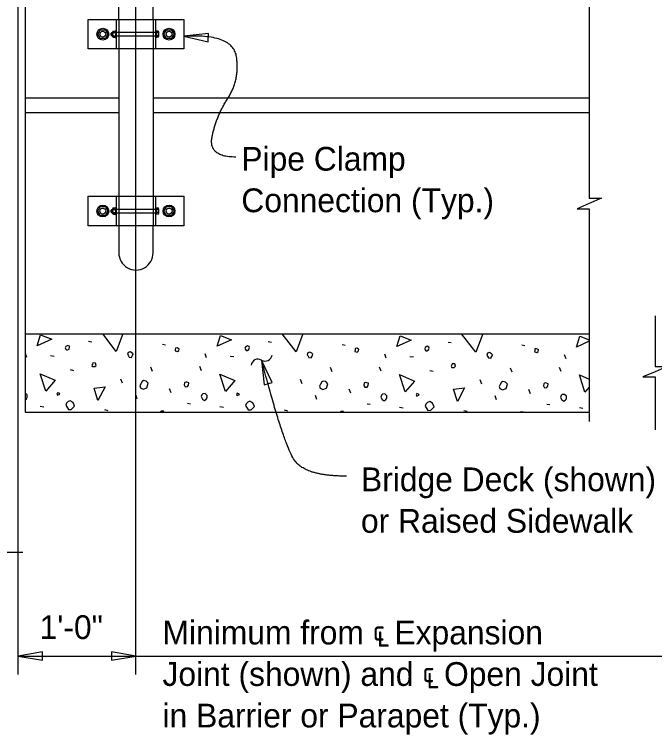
# Model space of a CAD drawing. Extents: x 0.2 to 40.8, y 0.5 to 25.7.
# Drawn here: x 23.58 to 29.01, y 10.82 to 16.93 of the extents above; entities that cross this region are included whole.
import ezdxf

# ---------------------------------------------------------------- set-up
doc = ezdxf.new("R2010")
doc.units = 0
for name, color, linetype in [('CL_Major', 7, 'Continuous'), ('Dimension', 7, 'Continuous'), ('Miscellaneous', 7, 'Continuous'), ('SteelMisc', 7, 'Continuous'), ('SteelMisc_h', 7, 'Continuous'), ('SupstrConc', 7, 'Continuous'), ('TextStructures', 7, 'Continuous')]:
    doc.layers.add(name, color=color, linetype=linetype)

msp = doc.modelspace()

# ---------------------------------------------------------------- linework, layer by layer
at = {"layer": 'CL_Major'}
for p, q in [((24.6151, 11.3358), (24.6151, 25.0052)), ((23.6151, 11.3358), (23.6151, 17.2313))]:
    msp.add_line(p, q, dxfattribs=at)
at = {"layer": 'Dimension'}
msp.add_line((23.6151, 11.4901), (29.4153, 11.4901), dxfattribs=at)
for points in [[(28.4596, 17.2246), (28.4596, 15.3737), (28.5629, 15.3737), (28.4596, 15.3287), (28.3562, 15.2837), (28.4596, 15.2837), (28.4596, 13.4788)], [(29.0176, 14.3746), (29.0176, 13.9474), (29.1209, 13.9474), (29.0176, 13.9024), (28.9142, 13.8574), (29.0176, 13.8574), (29.0176, 13.4079)], [(23.6547, 12.3699), (22.9577, 12.3699), (22.9577, 12.2536), (22.8583, 12.4786), (22.8583, 12.3699), (22.2031, 12.3699)]]:
    msp.add_lwpolyline(points, dxfattribs=at)
for points in [[(25.0211, 16.7461), (25.2271, 16.6998), (25.2309, 16.7703)], [(25.6811, 14.0008), (25.7034, 13.7907), (25.7713, 13.8098)], [(23.6151, 11.4901), (23.8234, 11.4549), (23.8234, 11.5254)], [(24.6151, 11.4902), (24.4069, 11.5255), (24.4069, 11.4549)]]:
    msp.add_lwpolyline(points, close=True, dxfattribs=at)
for centre, start, end in [((25.6504, 13.9489), 59.84335, 171.57057), ((25.7103, 14.052), 239.84335, 351.57057)]:
    msp.add_arc(centre, 0.0596, start, end, dxfattribs=at)
for points in [[(25.4627, 15.7225), (25.2257, 15.7202), (25.2971, 16.0714), (25.4956, 16.3764), (25.4402, 16.7692), (25.021, 16.7461)], [(26.3997, 13.0164), (26.0593, 13.0164), (25.8702, 13.2719), (25.6811, 14.0007)]]:
    msp.add_open_spline(points, degree=2, dxfattribs=at)
at = {"layer": 'Miscellaneous'}
for p, q in [((24.4075, 16.7575), (24.4075, 16.7696)), ((24.4132, 16.7575), (24.4132, 16.7696)), ((24.4075, 15.2575), (24.4075, 15.2696)), ((24.4132, 15.2575), (24.4132, 15.2696)), ((24.2137, 14.1609), (24.2402, 14.1556)), ((24.8395, 14.1361), (24.866, 14.1308)), ((25.7375, 14.1573), (25.7641, 14.152)), ((26.3633, 14.1326), (26.3898, 14.1273)), ((27.2613, 14.1538), (27.2879, 14.1485)), ((27.8871, 14.129), (27.9137, 14.1237)), ((23.6905, 14.023), (23.6781, 14.0566)), ((25.2143, 14.0194), (25.2019, 14.053)), ((26.7381, 14.0159), (26.7257, 14.0495)), ((23.8902, 14.0389), (23.922, 14.0353)), ((25.414, 14.0353), (25.4459, 14.0318)), ((26.9378, 14.0318), (26.9697, 14.0283)), ((28.2619, 14.0124), (28.2495, 14.046)), ((24.7564, 13.9045), (24.7423, 13.9399)), ((25.1718, 13.9098), (25.1577, 13.9452)), ((26.2802, 13.901), (26.2661, 13.9364)), ((26.6957, 13.9063), (26.6815, 13.9417)), ((27.8041, 13.8975), (27.7899, 13.9328)), ((28.2195, 13.9028), (28.2053, 13.9381)), ((24.0582, 13.9204), (24.0864, 13.9134)), ((27.1058, 13.9134), (27.1341, 13.9063)), ((24.5001, 13.8038), (24.486, 13.8391)), ((26.0239, 13.8002), (26.0098, 13.8356)), ((27.5477, 13.7967), (27.5336, 13.8321)), ((24.9138, 13.7225), (24.8996, 13.7578)), ((26.4376, 13.7189), (26.4234, 13.7543)), ((27.9614, 13.7154), (27.9472, 13.7507)), ((24.6256, 13.6712), (24.6132, 13.7048)), ((26.1494, 13.6677), (26.137, 13.7012)), ((27.6732, 13.6641), (27.6609, 13.6977)), ((25.0516, 13.6341), (25.0764, 13.6305)), ((26.5755, 13.6305), (26.6002, 13.627)), ((28.0993, 13.627), (28.124, 13.6235)), ((23.8036, 13.6093), (23.8336, 13.604)), ((24.3481, 13.581), (24.3764, 13.574)), ((25.3274, 13.6058), (25.3575, 13.6005)), ((25.8719, 13.5775), (25.9002, 13.5704)), ((26.8512, 13.6022), (26.8813, 13.5969)), ((27.3957, 13.574), (27.424, 13.5669)), ((28.375, 13.5987), (28.4051, 13.5934))]:
    msp.add_line(p, q, dxfattribs=at)
for points in [[(23.7788, 14.122), (23.8071, 14.2139), (23.9008, 14.1768), (23.7788, 14.122)], [(24.4488, 14.0742), (24.3346, 14.2245)], [(24.505, 14.2245), (24.4488, 14.0742)], [(25.3027, 14.1184), (25.3309, 14.2104), (25.4246, 14.1732), (25.3027, 14.1184)], [(25.9726, 14.0707), (25.8558, 14.2245)], [(26.0301, 14.2245), (25.9726, 14.0707)], [(26.8265, 14.1149), (26.8548, 14.2068), (26.9485, 14.1697), (26.8265, 14.1149)], [(27.4965, 14.0672), (27.3769, 14.2245)], [(27.5553, 14.2245), (27.4965, 14.0672)], [(28.3503, 14.1114), (28.3786, 14.2033), (28.4595, 14.1712)], [(24.0263, 14.0866), (24.0334, 14.0866), (24.0475, 14.0937), (24.0529, 14.1096), (24.0511, 14.1184), (24.0369, 14.1255), (24.0193, 14.1149), (24.0157, 14.1043), (24.0193, 14.0937), (24.0263, 14.0866)], [(25.5502, 14.0831), (25.5572, 14.0831), (25.5714, 14.0901), (25.5767, 14.1061), (25.5749, 14.1149), (25.5608, 14.122), (25.5431, 14.1114), (25.5395, 14.1008), (25.5431, 14.0901), (25.5502, 14.0831)], [(27.074, 14.0795), (27.081, 14.0795), (27.0952, 14.0866), (27.1005, 14.1025), (27.0987, 14.1114), (27.0846, 14.1184), (27.0669, 14.1078), (27.0634, 14.0972), (27.0669, 14.0866), (27.074, 14.0795)], [(28.4595, 14.1604), (28.3503, 14.1114)], [(24.5478, 14.0424), (24.5567, 14.0265), (24.5779, 14.023), (24.5867, 14.0389), (24.5903, 14.053), (24.5814, 14.0619), (24.5655, 14.0707), (24.5496, 14.0654), (24.5443, 14.0495), (24.5478, 14.0424)], [(24.9473, 14.0778), (24.9668, 14.0725), (24.9792, 14.0813), (24.9809, 14.0937), (24.9774, 14.0972), (24.9633, 14.1043), (24.9509, 14.1025), (24.9491, 14.0901), (24.9473, 14.0778)], [(26.0716, 14.0389), (26.0805, 14.023), (26.1017, 14.0194), (26.1105, 14.0353), (26.1141, 14.0495), (26.1052, 14.0583), (26.0893, 14.0672), (26.0734, 14.0619), (26.0681, 14.046), (26.0716, 14.0389)], [(26.4712, 14.0742), (26.4906, 14.0689), (26.503, 14.0778), (26.5047, 14.0901), (26.5012, 14.0937), (26.4871, 14.1008), (26.4747, 14.099), (26.4729, 14.0866), (26.4712, 14.0742)], [(27.5955, 14.0353), (27.6043, 14.0194), (27.6255, 14.0159), (27.6343, 14.0318), (27.6379, 14.046), (27.629, 14.0548), (27.6131, 14.0636), (27.5972, 14.0583), (27.5919, 14.0424), (27.5955, 14.0353)], [(27.995, 14.0707), (28.0144, 14.0654), (28.0268, 14.0742), (28.0286, 14.0866), (28.025, 14.0901), (28.0109, 14.0972), (27.9985, 14.0954), (27.9967, 14.0831), (27.995, 14.0707)], [(24.2455, 13.9452), (24.2668, 13.9452), (24.2774, 13.9558), (24.2721, 13.9752), (24.2491, 13.977), (24.2455, 13.9664), (24.2402, 13.9576), (24.2455, 13.9452), (24.242, 13.9487)], [(27.2932, 13.9381), (27.3144, 13.9381), (27.325, 13.9487), (27.3197, 13.9682), (27.2967, 13.9699), (27.2932, 13.9593), (27.2879, 13.9505), (27.2932, 13.9381), (27.2896, 13.9417)], [(23.8513, 13.7384), (23.8036, 13.8851), (23.9291, 13.8303), (23.8513, 13.7384)], [(25.3751, 13.7348), (25.3274, 13.8815), (25.4529, 13.8267), (25.3751, 13.7348)], [(26.899, 13.7313), (26.8512, 13.878), (26.9767, 13.8232), (26.899, 13.7313)], [(28.4228, 13.7278), (28.375, 13.8745), (28.4595, 13.8376)], [(24.6539, 13.7666), (24.6769, 13.7543), (24.7069, 13.7666), (24.7193, 13.8038), (24.7016, 13.8214), (24.6786, 13.8267), (24.668, 13.8197), (24.6557, 13.8002), (24.6468, 13.7843), (24.6539, 13.7666)], [(25.0234, 13.7896), (25.0322, 13.7737), (25.0516, 13.7755), (25.0605, 13.7879), (25.0622, 13.8073), (25.0499, 13.8126), (25.041, 13.8144), (25.0304, 13.8108), (25.0269, 13.8073), (25.0234, 13.7896)], [(26.1777, 13.7631), (26.2007, 13.7507), (26.2307, 13.7631), (26.2431, 13.8002), (26.2254, 13.8179), (26.2025, 13.8232), (26.1919, 13.8161), (26.1795, 13.7967), (26.1706, 13.7808), (26.1777, 13.7631)], [(26.5472, 13.7861), (26.556, 13.7702), (26.5755, 13.7719), (26.5843, 13.7843), (26.5861, 13.8038), (26.5737, 13.8091), (26.5648, 13.8108), (26.5542, 13.8073), (26.5507, 13.8038), (26.5472, 13.7861)], [(27.7015, 13.7596), (27.7245, 13.7472), (27.7546, 13.7596), (27.7669, 13.7967), (27.7493, 13.8144), (27.7263, 13.8197), (27.7157, 13.8126), (27.7033, 13.7932), (27.6945, 13.7773), (27.7015, 13.7596)], [(28.071, 13.7826), (28.0798, 13.7666), (28.0993, 13.7684), (28.1081, 13.7808), (28.1099, 13.8002), (28.0975, 13.8055), (28.0887, 13.8073), (28.0781, 13.8038), (28.0745, 13.8002), (28.071, 13.7826)], [(28.9269, 13.863), (28.9241, 13.8574)], [(24.2933, 13.657), (24.2597, 13.7613), (24.3534, 13.7737), (24.2933, 13.657)], [(27.3409, 13.65), (27.3073, 13.7543), (27.401, 13.7666), (27.3409, 13.65)], [(28.4595, 13.7712), (28.4228, 13.7278)], [(23.6763, 13.665), (23.6869, 13.673), (23.694, 13.6836), (23.694, 13.7048), (23.6781, 13.7207), (23.6763, 13.7205)], [(23.9503, 13.703), (23.9698, 13.7118), (23.9627, 13.7189), (23.9503, 13.7242), (23.945, 13.7118), (23.9503, 13.703)], [(25.1683, 13.6906), (25.1789, 13.6694), (25.1966, 13.6588), (25.2107, 13.6694), (25.2178, 13.68), (25.2178, 13.7012), (25.2019, 13.7171), (25.1825, 13.7154), (25.1736, 13.7065), (25.1683, 13.6906)], [(25.4741, 13.6995), (25.4936, 13.7083), (25.4865, 13.7154), (25.4741, 13.7207), (25.4688, 13.7083), (25.4741, 13.6995)], [(26.6921, 13.6871), (26.7027, 13.6659), (26.7204, 13.6553), (26.7346, 13.6659), (26.7416, 13.6765), (26.7416, 13.6977), (26.7257, 13.7136), (26.7063, 13.7118), (26.6974, 13.703), (26.6921, 13.6871)], [(26.998, 13.6959), (27.0174, 13.7048), (27.0103, 13.7118), (26.998, 13.7171), (26.9926, 13.7048), (26.998, 13.6959)], [(28.2159, 13.6836), (28.2266, 13.6623), (28.2442, 13.6517), (28.2584, 13.6623), (28.2654, 13.673), (28.2654, 13.6942), (28.2495, 13.7101), (28.2301, 13.7083), (28.2212, 13.6995), (28.2159, 13.6836)], [(24.021, 13.6182), (24.044, 13.581), (24.067, 13.5828), (24.0758, 13.5916), (24.0953, 13.6111), (24.0829, 13.6411), (24.0582, 13.6553), (24.0405, 13.6482), (24.0263, 13.6341), (24.021, 13.6182)], [(25.5448, 13.6146), (25.5678, 13.5775), (25.5908, 13.5793), (25.5996, 13.5881), (25.6191, 13.6075), (25.6067, 13.6376), (25.582, 13.6517), (25.5643, 13.6447), (25.5502, 13.6305), (25.5448, 13.6146)], [(27.0687, 13.6111), (27.0916, 13.574), (27.1146, 13.5757), (27.1235, 13.5846), (27.1429, 13.604), (27.1305, 13.6341), (27.1058, 13.6482), (27.0881, 13.6411), (27.074, 13.627), (27.0687, 13.6111)], [(24.8519, 13.5578), (24.8501, 13.5669), (24.8413, 13.5687), (24.8289, 13.5669), (24.8198, 13.5578)], [(26.375, 13.5578), (26.3739, 13.5634), (26.3651, 13.5651), (26.3527, 13.5634), (26.3472, 13.5578)], [(27.8981, 13.5578), (27.8977, 13.5598), (27.8889, 13.5616), (27.8765, 13.5598), (27.8745, 13.5578)]]:
    msp.add_lwpolyline(points, dxfattribs=at)
at = {"layer": 'SteelMisc'}
for p, q in [((24.4692, 16.8894), (24.4692, 23.2644)), ((24.7609, 16.8894), (24.7609, 23.2644)), ((24.2091, 16.8894), (25.021, 16.8894)), ((24.2091, 16.6394), (24.2091, 16.8894)), ((24.4484, 16.8894), (24.4484, 16.6394)), ((24.7817, 16.8894), (24.7817, 16.6394)), ((25.021, 16.8894), (25.021, 16.6394)), ((24.4418, 16.7947), (24.4418, 16.734)), ((24.4418, 16.7947), (24.4484, 16.7947)), ((24.788, 16.7947), (24.782, 16.7947)), ((24.788, 16.7947), (24.788, 16.734)), ((24.4047, 16.7724), (24.4103, 16.7789)), ((24.4047, 16.7547), (24.4047, 16.7724)), ((24.4047, 16.7547), (24.4103, 16.749)), ((24.4103, 16.7789), (24.4168, 16.7789)), ((24.4103, 16.749), (24.4103, 16.7789)), ((24.4103, 16.749), (24.4168, 16.749)), ((24.4168, 16.7823), (24.4168, 16.7465)), ((24.4215, 16.7774), (24.4418, 16.7774)), ((24.4215, 16.7514), (24.4418, 16.7514)), ((24.4217, 16.7904), (24.4418, 16.7904)), ((24.4218, 16.7384), (24.4418, 16.7384)), ((24.4418, 16.7904), (24.4418, 16.7384)), ((24.4418, 16.734), (24.4484, 16.734)), ((24.788, 16.734), (24.782, 16.734)), ((24.8027, 16.7903), (24.788, 16.7903)), ((24.8028, 16.7773), (24.788, 16.7773)), ((24.8028, 16.7514), (24.788, 16.7514)), ((24.8027, 16.7384), (24.788, 16.7384)), ((24.8078, 16.745), (24.8078, 16.7838)), ((25.021, 16.6394), (24.2091, 16.6394)), ((24.4692, 16.6394), (24.4692, 15.3894)), ((24.7609, 16.6394), (24.7609, 15.3894)), ((24.2091, 15.3894), (25.021, 15.3894)), ((24.2091, 15.1394), (24.2091, 15.3894)), ((24.4484, 15.3894), (24.4484, 15.1394)), ((24.7817, 15.3894), (24.7817, 15.1394)), ((25.021, 15.3894), (25.021, 15.1394)), ((24.4047, 15.2724), (24.4103, 15.2789)), ((24.4047, 15.2547), (24.4047, 15.2724)), ((24.4103, 15.2789), (24.4168, 15.2789)), ((24.4103, 15.249), (24.4103, 15.2789)), ((24.4168, 15.2823), (24.4168, 15.2465)), ((24.4215, 15.2774), (24.4418, 15.2774)), ((24.4217, 15.2904), (24.4418, 15.2904)), ((24.4418, 15.2947), (24.4418, 15.234)), ((24.4418, 15.2947), (24.4484, 15.2947)), ((24.4418, 15.2904), (24.4418, 15.2384)), ((24.788, 15.2947), (24.782, 15.2947)), ((24.788, 15.2947), (24.788, 15.234)), ((24.8027, 15.2903), (24.788, 15.2903)), ((24.8028, 15.2773), (24.788, 15.2773)), ((24.8078, 15.245), (24.8078, 15.2838)), ((24.4047, 15.2547), (24.4103, 15.249)), ((24.4103, 15.249), (24.4168, 15.249)), ((24.4215, 15.2514), (24.4418, 15.2514)), ((24.4218, 15.2384), (24.4418, 15.2384)), ((24.4418, 15.234), (24.4484, 15.234)), ((24.788, 15.234), (24.782, 15.234)), ((24.8028, 15.2514), (24.788, 15.2514)), ((24.8027, 15.2384), (24.788, 15.2384)), ((25.021, 15.1394), (24.2091, 15.1394)), ((24.4692, 15.1394), (24.4692, 14.9102)), ((24.7609, 14.9102), (24.7609, 15.1394))]:
    msp.add_line(p, q, dxfattribs=at)
for points in [[(24.3124, 16.8019), (24.3557, 16.8019), (24.3774, 16.7644), (24.3557, 16.7269), (24.3124, 16.7269), (24.2907, 16.7644)], [(24.8744, 16.8019), (24.9177, 16.8019), (24.9394, 16.7644), (24.9177, 16.7269), (24.8744, 16.7269), (24.8527, 16.7644)], [(24.3124, 15.3019), (24.3557, 15.3019), (24.3774, 15.2644), (24.3557, 15.2269), (24.3124, 15.2269), (24.2907, 15.2644)], [(24.8744, 15.3019), (24.9177, 15.3019), (24.9394, 15.2644), (24.9177, 15.2269), (24.8744, 15.2269), (24.8527, 15.2644)]]:
    msp.add_lwpolyline(points, close=True, dxfattribs=at)
for centre, radius in [((24.3341, 16.7644), 0.05), ((24.896, 16.7644), 0.05), ((24.3341, 16.7644), 0.025), ((24.896, 16.7644), 0.025), ((24.3341, 15.2644), 0.05), ((24.3341, 15.2644), 0.025), ((24.896, 15.2644), 0.05), ((24.896, 15.2644), 0.025)]:
    msp.add_circle(centre, radius, dxfattribs=at)
for centre, radius, start, end in [((24.4234, 16.7838), 0.00674, 104.48908, 254.18889), ((24.4363, 16.7644), 0.0196, 138.62797, 221.37203), ((24.4234, 16.7449), 0.00673, 105.7823, 255.54039), ((24.801, 16.7838), 0.00673, 285.7823, 75.54039), ((24.801, 16.7449), 0.00674, 284.48908, 74.18889), ((24.7881, 16.7644), 0.0196, 318.62797, 41.37203), ((24.4234, 15.2838), 0.00674, 104.48908, 254.18889), ((24.4363, 15.2644), 0.0196, 138.62797, 221.37203), ((24.801, 15.2838), 0.00673, 285.7823, 75.54039), ((24.7881, 15.2644), 0.0196, 318.62797, 41.37203), ((24.4234, 15.2449), 0.00673, 105.7823, 255.54039), ((24.801, 15.2449), 0.00674, 284.48908, 74.18889)]:
    msp.add_arc(centre, radius, start, end, dxfattribs=at)
msp.add_ellipse((24.6151, 14.9102), major_axis=(0, 0.1458), ratio=0.999499, start_param=1.570796, end_param=4.712389, dxfattribs=at)
at = {"layer": 'SteelMisc_h'}
for p, q in [((24.4692, 16.8894), (24.4692, 16.6394)), ((24.7609, 16.8894), (24.7609, 16.6394)), ((24.7817, 16.7789), (24.4168, 16.7789)), ((24.4168, 16.749), (24.7817, 16.749)), ((24.4692, 15.3894), (24.4692, 15.1394)), ((24.7609, 15.3894), (24.7609, 15.1394)), ((24.7817, 15.2789), (24.4168, 15.2789)), ((24.4168, 15.249), (24.7817, 15.249))]:
    msp.add_line(p, q, dxfattribs=at)
at = {"layer": 'SupstrConc'}
for p, q in [((23.6763, 17.2245), (23.6763, 13.5578)), ((23.6763, 16.2245), (24.4692, 16.2245)), ((24.7609, 16.2245), (28.4595, 16.2245)), ((24.7609, 16.2245), (26.002, 16.2245)), ((23.6763, 16.0995), (24.4692, 16.0995)), ((24.7609, 16.0995), (28.4596, 16.0995)), ((23.6763, 14.2245), (28.4595, 14.2245)), ((23.6763, 13.5578), (28.4595, 13.5578))]:
    msp.add_line(p, q, dxfattribs=at)

# ---------------------------------------------------------------- texts
at = {"layer": 'Dimension'}
for s, p in [('Pipe Clamp ', (25.5087, 15.6066)), ('Connection (Typ.)', (25.5087, 15.2546)), ('Bridge Deck (shown)', (26.5232, 12.8886)), ('or Raised Sidewalk', (26.5232, 12.5366)), ('Minimum from ℄ Expansion', (24.8405, 11.5897)), ('Joint (shown) and ℄ Open Joint ', (24.8405, 11.2377)), ('in Barrier or Parapet (Typ.)', (24.8405, 10.8857))]:
    msp.add_text(s, height=0.2016, dxfattribs=at).set_placement(p)
at = {"layer": 'TextStructures'}
msp.add_text('1\'-0"', height=0.2016, dxfattribs=at).set_placement((23.7982, 11.6351))

doc.saveas('drawing.dxf')
